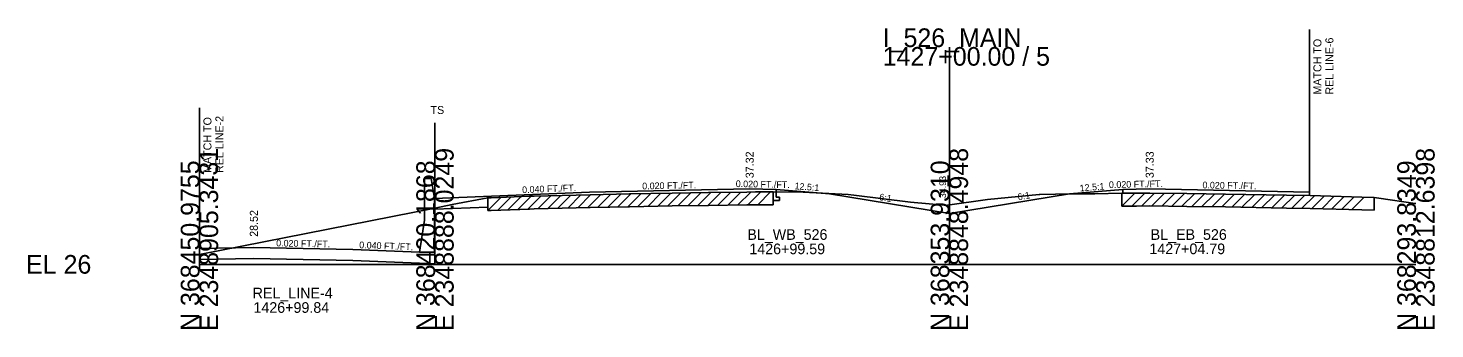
# Model space of a CAD drawing. Extents: x -170 to 2527928, y -10 to 1619750.
# Drawn here: x 3974.3 to 4185.3, y 4990.3 to 5035.5 of the extents above; entities that cross this region are included whole.
import ezdxf

# ---------------------------------------------------------------- set-up
doc = ezdxf.new("R2010")
doc.units = 0
for name, color, linetype in [('RD_GPK_XS_Cell', 7, 'Continuous'), ('RD_PD_NOISE-WALL-GM', 7, 'Continuous'), ('RD_XS_Base', 7, 'Continuous'), ('RD_XS_EarthShd', 7, 'Continuous'), ('RD_XS_ExGround', 7, 'Continuous'), ('RD_XS_ExPaveRet', 7, 'Continuous'), ('RD_XS_MatchLine', 7, 'Continuous'), ('RD_XS_Pave', 7, 'Continuous'), ('RD_XS_PaveShd', 7, 'Continuous'), ('RD_XS_TieSlope', 7, 'Continuous'), ('RD_XS_TX_Elev_EX', 7, 'Continuous'), ('RD_XS_TX_Slope', 7, 'Continuous'), ('RD_XS_TX_Station', 7, 'Continuous')]:
    doc.layers.add(name, color=color, linetype=linetype)

msp = doc.modelspace()

# ---------------------------------------------------------------- linework, layer by layer
at = {"layer": 'RD_GPK_XS_Cell'}
for p, q in [((4112.48, 5000), (4112.48, 5032.63)), ((4000, 5000), (4035.33, 5000)), ((4035.33, 5000), (4112.48, 5000)), ((4112.48, 5000), (4182.46, 5000))]:
    msp.add_line(p, q, dxfattribs=at)
at = {"layer": 'RD_PD_NOISE-WALL-GM'}
for p, q in [((4033.77, 5012.91), (4034.77, 5012.91)), ((4033.77, 5012.91), (4033.77, 5006.64)), ((4034.77, 5012.91), (4035.25, 5009.91)), ((4035.26, 5001.82), (4035.25, 5009.91)), ((4032.99, 5001.82), (4033.77, 5006.64)), ((4032.99, 5001.82), (4035.26, 5001.82))]:
    msp.add_line(p, q, dxfattribs=at)
at = {"layer": 'RD_XS_Base'}
for p, q in [((4086.48, 5010.11), (4086.48, 5011.24)), ((4138.48, 5010.67), (4138.48, 5011.25)), ((4043.24, 5008.6), (4043.24, 5010.23)), ((4086.04, 5009.61), (4086.48, 5009.61)), ((4086.98, 5010.1), (4086.48, 5010.11)), ((4086.48, 5009.61), (4086.98, 5009.6)), ((4086.98, 5009.6), (4086.98, 5010.1)), ((4166.48, 5010.33), (4166.48, 5010.85)), ((4035.32, 5008.28), (4043.24, 5008.6)), ((4000, 5000.72), (4008.1, 5000.88)), ((4008.1, 5000.88), (4022.99, 5000.59)), ((4022.99, 5000.59), (4032.99, 5000.19)), ((4032.99, 5000.19), (4035.33, 5000.09))]:
    msp.add_line(p, q, dxfattribs=at)
at = {"layer": 'RD_XS_EarthShd'}
for p, q in [((4086.48, 5011.24), (4094.48, 5010.6)), ((4138.48, 5011.25), (4130.48, 5010.61))]:
    msp.add_line(p, q, dxfattribs=at)
at = {"layer": 'RD_XS_ExGround'}
msp.add_lwpolyline([(4000, 5001.5), (4035.33, 5008.46), (4037.93, 5008.97), (4043.24, 5009.98), (4043.75, 5010), (4049.48, 5010.22), (4050.2, 5010.24), (4058.62, 5010.46), (4064.5, 5010.57), (4070.92, 5010.7), (4076.35, 5010.77), (4082.08, 5010.85), (4083.38, 5010.87), (4086.04, 5010.88), (4090.57, 5010.82), (4097.31, 5010.5), (4098.13, 5010.41), (4106.65, 5009.36), (4111.72, 5008.89), (4111.98, 5008.86), (4112.22, 5008.9), (4118.18, 5009.74), (4125.95, 5010.5), (4125.96, 5010.5), (4125.99, 5010.5), (4126.07, 5010.5), (4130.75, 5010.61), (4134.29, 5010.61), (4138.35, 5010.67), (4140.53, 5010.68), (4142.56, 5010.7), (4148.1, 5010.62), (4153.89, 5010.54), (4163.03, 5010.38), (4166.6, 5010.32), (4174.32, 5010.11), (4176.18, 5010.05), (4176.9, 5009.96), (4182.36, 5009.16), (4182.46, 5009.14)], dxfattribs=at)
at = {"layer": 'RD_XS_ExPaveRet'}
for p, q in [((4043.24, 5008.07), (4045.23, 5010.06)), ((4043.24, 5008.07), (4043.24, 5009.98)), ((4044.74, 5008.12), (4046.73, 5010.11)), ((4046.24, 5008.18), (4048.23, 5010.17)), ((4047.74, 5008.24), (4049.73, 5010.23)), ((4049.24, 5008.29), (4051.21, 5010.26)), ((4050.74, 5008.34), (4052.71, 5010.31)), ((4052.24, 5008.38), (4054.21, 5010.35)), ((4053.74, 5008.42), (4055.71, 5010.39)), ((4055.24, 5008.46), (4057.21, 5010.43)), ((4056.74, 5008.5), (4058.71, 5010.47)), ((4058.24, 5008.54), (4060.2, 5010.49)), ((4059.74, 5008.57), (4061.69, 5010.52)), ((4061.24, 5008.6), (4063.19, 5010.55)), ((4062.74, 5008.62), (4064.69, 5010.58)), ((4064.24, 5008.65), (4066.19, 5010.61)), ((4065.74, 5008.68), (4067.69, 5010.64)), ((4067.24, 5008.71), (4069.19, 5010.67)), ((4068.74, 5008.74), (4070.69, 5010.69)), ((4070.24, 5008.77), (4072.19, 5010.72)), ((4071.74, 5008.79), (4073.68, 5010.74)), ((4073.24, 5008.81), (4075.18, 5010.76)), ((4074.74, 5008.83), (4076.68, 5010.78)), ((4076.24, 5008.85), (4078.18, 5010.8)), ((4076.35, 5008.86), (4082.08, 5008.93)), ((4077.74, 5008.88), (4079.68, 5010.82)), ((4079.24, 5008.9), (4081.18, 5010.84)), ((4080.74, 5008.92), (4082.68, 5010.86)), ((4082.08, 5008.93), (4083.38, 5008.95)), ((4082.24, 5008.94), (4084.18, 5010.87)), ((4083.38, 5008.95), (4086.04, 5008.96)), ((4083.74, 5008.96), (4085.66, 5010.88)), ((4086.04, 5010.88), (4086.04, 5008.96)), ((4138.35, 5008.75), (4140.28, 5010.68)), ((4138.35, 5008.75), (4138.35, 5010.67)), ((4139.85, 5008.76), (4141.78, 5010.69)), ((4141.35, 5008.77), (4143.27, 5010.69)), ((4142.85, 5008.78), (4144.74, 5010.67)), ((4144.35, 5008.76), (4146.24, 5010.65)), ((4145.85, 5008.74), (4147.74, 5010.63)), ((4147.35, 5008.72), (4149.24, 5010.61)), ((4148.85, 5008.69), (4150.74, 5010.58)), ((4150.35, 5008.67), (4152.24, 5010.56)), ((4151.85, 5008.65), (4153.74, 5010.54)), ((4153.35, 5008.63), (4155.24, 5010.52)), ((4154.85, 5008.6), (4156.73, 5010.49)), ((4156.35, 5008.58), (4158.23, 5010.46)), ((4157.85, 5008.55), (4159.73, 5010.44)), ((4159.35, 5008.53), (4161.23, 5010.41)), ((4160.85, 5008.5), (4162.73, 5010.39)), ((4162.35, 5008.48), (4164.24, 5010.36)), ((4163.85, 5008.45), (4165.74, 5010.34)), ((4165.35, 5008.43), (4167.23, 5010.31)), ((4166.85, 5008.4), (4168.71, 5010.26)), ((4168.35, 5008.36), (4170.21, 5010.22)), ((4169.85, 5008.32), (4171.71, 5010.18)), ((4171.35, 5008.27), (4173.21, 5010.14)), ((4172.85, 5008.23), (4174.71, 5010.09)), ((4176.18, 5010.05), (4176.18, 5008.13)), ((4043.24, 5008.07), (4043.75, 5008.08)), ((4043.75, 5008.08), (4049.48, 5008.3)), ((4049.48, 5008.3), (4050.2, 5008.32)), ((4050.2, 5008.32), (4058.62, 5008.55)), ((4058.62, 5008.55), (4064.5, 5008.66)), ((4064.5, 5008.66), (4070.92, 5008.78)), ((4070.92, 5008.78), (4076.35, 5008.86)), ((4138.35, 5008.75), (4140.53, 5008.76)), ((4140.53, 5008.76), (4142.56, 5008.78)), ((4142.56, 5008.78), (4148.1, 5008.71)), ((4148.1, 5008.71), (4153.89, 5008.62)), ((4153.89, 5008.62), (4163.03, 5008.46)), ((4163.03, 5008.46), (4166.6, 5008.41)), ((4166.6, 5008.41), (4174.32, 5008.19)), ((4174.32, 5008.19), (4176.18, 5008.13))]:
    msp.add_line(p, q, dxfattribs=at)
at = {"layer": 'RD_XS_MatchLine'}
for p, q in [((4166.48, 5010.85), (4166.48, 5035.26)), ((4000, 4999.09), (4000, 5023.5)), ((4035.33, 5000), (4035.33, 5021.24))]:
    msp.add_line(p, q, dxfattribs=at)
at = {"layer": 'RD_XS_Pave'}
for p, q in [((4058.48, 5010.84), (4082.48, 5011.32)), ((4142.48, 5011.33), (4166.48, 5010.85)), ((4008.1, 5002.52), (4022.99, 5002.22))]:
    msp.add_line(p, q, dxfattribs=at)
at = {"layer": 'RD_XS_PaveShd'}
for p, q in [((4082.48, 5011.32), (4086.48, 5011.24)), ((4138.48, 5011.25), (4142.48, 5011.33)), ((4035.25, 5009.91), (4058.48, 5010.84)), ((4000, 5002.36), (4008.1, 5002.52)), ((4000, 5002.36), (4000, 5001.5)), ((4022.99, 5002.22), (4032.99, 5001.82))]:
    msp.add_line(p, q, dxfattribs=at)
at = {"layer": 'RD_XS_TieSlope'}
for p in [(4094.48, 5010.6), (4130.48, 5010.61)]:
    msp.add_line(p, (4112.48, 5007.61), dxfattribs=at)

# ---------------------------------------------------------------- texts
at = {"layer": 'RD_GPK_XS_Cell'}
for s, p in [('I_526_MAIN', (4102.48, 5032.63)), ('1427+00.00 / 5', (4102.48, 5029.83)), ('EL 26', (3974, 4998.6))]:
    msp.add_text(s, height=2.8, dxfattribs=at).set_placement(p)
for s, p in [('N 368450.9755', (4000, 4990)), ('E 2348905.3431', (4002.8, 4990)), ('N 368420.1868', (4035.33, 4990)), ('E 2348888.0249', (4038.13, 4990)), ('N 368353.9310', (4112.48, 4990)), ('E 2348848.4948', (4115.28, 4990)), ('N 368293.8349', (4182.46, 4990)), ('E 2348812.6398', (4185.26, 4990))]:
    msp.add_text(s, height=2.8, rotation=90, dxfattribs=at).set_placement(p)
at = {"layer": 'RD_XS_MatchLine'}
msp.add_text('TS', height=1.2, dxfattribs=at).set_placement((4034.66, 5022.58))
at = {"layer": 'RD_XS_TX_Elev_EX'}
msp.add_text('34.93', height=1, rotation=90, dxfattribs=at).set_placement((4111.98, 5009.93))
at = {"layer": 'RD_XS_TX_Slope'}
for s, rotation, p in [('0.040 FT./FT.', 2.2906, (4048.42, 5010.69)), ('0.020 FT./FT.', 1.1458, (4066.42, 5011.25)), ('0.020 FT./FT.', 358.8542, (4080.43, 5011.61)), ('12.5:1', 355.4261, (4089.23, 5011.28)), ('12.5:1', 4.5739, (4132.06, 5010.94)), ('0.020 FT./FT.', 1.1458, (4136.42, 5011.46)), ('0.020 FT./FT.', 358.8542, (4150.43, 5011.42)), ('6:1', 350.5377, (4101.9, 5009.66)), ('6:1', 9.4623, (4122.81, 5009.61)), ('0.020 FT./FT.', 358.8542, (4011.5, 5002.7)), ('0.040 FT./FT.', 357.7094, (4023.95, 5002.43))]:
    msp.add_text(s, height=1, rotation=rotation, dxfattribs=at).set_placement(p)
at = {"layer": 'RD_XS_TX_Station'}
for s, p in [('MATCH TO', (4168.28, 5025.49)), ('REL LINE-6', (4170.08, 5025.49)), ('MATCH TO', (4001.8, 5013.73)), ('REL LINE-2', (4003.6, 5013.73)), (' 37.32', (4083.13, 5012.49)), (' 37.33', (4143.13, 5012.5)), (' 28.52', (4008.76, 5003.69))]:
    msp.add_text(s, height=1.2, rotation=90, dxfattribs=at).set_placement(p)
for s, p in [('BL_WB_526', (4082.18, 5003.68)), ('BL_EB_526', (4142.67, 5003.68)), ('1426+99.59', (4082.48, 5001.52)), ('1427+04.79', (4142.48, 5001.53)), ('REL_LINE-4', (4007.98, 4994.89)), ('1426+99.84', (4008.1, 4992.72))]:
    msp.add_text(s, height=1.6, dxfattribs=at).set_placement(p)

doc.saveas('drawing.dxf')
